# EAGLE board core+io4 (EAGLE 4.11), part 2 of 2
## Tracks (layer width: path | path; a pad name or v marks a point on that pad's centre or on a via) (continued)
N$97
  Bottom 0.254: IC6.2 17.77,68.41 16.5,67.14 12.06,67.14 11.43,67.78 10.16,67.78 8.89,69.05 OUT5-6.10
N$98  (via drill 0.61)
  Top 0.254: v26.03,74.13 26.03,70.32 IC6.5
  Bottom 0.254: v26.03,74.13 19.68,74.13 19.04,73.5 12.06,73.5 11.43,72.86 9.52,72.86 8.89,72.22 8.25,72.22 OUT5-6.12
N$99
  Bottom 0.254: IC6.6 27.93,69.69 26.66,70.95 14.6,70.95 13.97,70.32 7.62,70.32 6.98,70.95 6.98,74.13 7.62,74.13 OUT5-6.14
N$100  (via drill 0.61)
  Top 0.254: v19.68,58.89 v19.68,65.88 | v5.71,53.81 5.71,75.4 v5.08,76.03
  Bottom 0.254: v19.68,65.88 20.95,67.14 35.55,67.14 36.19,67.78 IC6.9 | v19.68,58.89 19.68,55.08 17.77,53.17 8.25,53.17 7.62,53.81 v5.71,53.81 | v5.08,76.03 5.71,76.03 6.34,76.67 7.62,76.67 OUT5-6.16
N$101
  Bottom 0.254: IC15.3 95.24,56.98 96.52,58.25 104.13,58.25 104.77,58.89 116.83,58.89 IN5-6.2
N$102  (via drill 0.61)
  Top 0.254: v97.15,61.43 97.15,57.62 IC15.4
  Bottom 0.254: v97.15,61.43 103.5,61.43 104.77,60.16 106.04,60.16 106.67,60.8 117.47,60.8 IN5-6.4
N$103  (via drill 0.61)
  Top 0.254: v116.2,57.62 115.56,58.25 115.56,62.7 116.83,63.97 IN5-6.6
  Bottom 0.254: v116.2,57.62 115.56,58.25 105.41,58.25 104.77,57.62 IC15.7
N$104  (via drill 0.61)
  Top 0.254: v108.58,65.88 108.58,58.89 107.94,58.25 107.94,56.98 IC15.8
  Bottom 0.254: v108.58,65.88 109.21,66.51 116.83,66.51 IN5-6.8
N$105
  Bottom 0.254: IC16.13 106.67,76.03 103.5,72.86 103.5,72.22 104.13,72.22 105.41,70.95 116.2,70.95 116.83,70.32 118.1,70.32 119.38,69.05 IN5-6.9
N$106  (via drill 0.61)
  Top 0.254: v104.77,83.02 104.77,77.94 IC16.14 | v118.74,83.02 118.74,72.22 119.38,71.59 IN5-6.11
  Bottom 0.254: v104.77,83.02 v118.74,83.02
N$107  (via drill 0.61)
  Top 0.254: v98.42,100.16 98.42,84.29 97.78,83.66 97.78,77.3 IC16.17 | v130.81,100.16 130.81,93.18 130.17,92.55 130.17,74.77 v129.53,74.13
  Bottom 0.254: v98.42,100.16 99.05,99.53 113.66,99.53 114.93,100.8 118.74,100.8 120.01,99.53 130.17,99.53 v130.81,100.16 | v129.53,74.13 120.64,74.13 IN5-6.13
N$108
  Bottom 0.254: IC16.18 95.24,77.3 96.52,78.58 118.74,78.58 120.01,77.3 IN5-6.15
N$109  (via drill 0.61)
  Top 0.254: v104.13,59.52 104.77,60.16 104.77,61.43 106.67,63.34 IC15.13
  Bottom 0.254: v104.13,59.52 106.67,59.52 107.31,60.16 118.1,60.16 118.74,59.52 120.01,59.52 IN5-6.1
N$110  (via drill 0.61)
  Top 0.254: v121.28,79.21 121.28,76.03 120.64,75.4 121.28,74.77 121.28,62.06 120.64,61.43 IN5-6.3 | v106.04,79.84 106.04,72.22 105.41,71.59 105.41,70.95 106.04,70.32 106.04,67.78 104.77,66.51 104.77,65.24 IC15.14
  Bottom 0.254: v121.28,79.21 106.67,79.21 v106.04,79.84
N$111
  Bottom 0.254: IC15.17 97.78,63.34 99.05,62.06 105.41,62.06 106.04,62.7 106.67,62.06 113.66,62.06 116.83,65.24 118.1,65.24 119.38,63.97 IN5-6.5
N$112  (via drill 0.61)
  Top 0.254: v135.88,66.51 136.52,67.14 136.52,67.78 137.16,68.41 137.16,79.84 136.52,80.48 136.52,84.29 v133.98,86.83 | v108.58,87.47 108.58,74.77 109.21,74.13 109.21,70.95 108.58,70.32 108.58,67.78 106.67,65.88 v106.04,65.88
  Bottom 0.254: v135.88,66.51 120.64,66.51 IN5-6.7 | v133.98,86.83 133.34,86.19 114.3,86.19 113.02,87.47 v108.58,87.47 | v106.04,65.88 105.41,66.51 95.88,66.51 94.61,65.24 IC15.18
N$113
  Bottom 0.254: IC8.19 17.77,101.44 16.5,100.16 13.33,100.16 11.43,102.07 OUT7-8.15
N$114
  Bottom 0.254: IC8.16 25.39,101.44 24.12,100.16 17.77,100.16 17.14,99.53 11.43,99.53 OUT7-8.13
N$115
  Bottom 0.254: IC8.15 28.57,100.8 28.57,98.26 12.7,98.26 11.43,96.99 OUT7-8.11
N$116  (via drill 0.61)
  Top 0.254: v12.06,103.97 12.06,95.08 11.43,94.45 OUT7-8.9
  Bottom 0.254: v12.06,103.97 12.7,104.61 34.92,104.61 36.19,103.34 IC8.12
N$117
  Bottom 0.254: IC8.2 17.77,93.81 16.5,92.55 12.06,92.55 11.43,93.18 10.16,93.18 8.89,94.45 OUT7-8.10
N$118  (via drill 0.61)
  Top 0.254: v26.03,99.53 26.03,95.72 IC8.5
  Bottom 0.254: v26.03,99.53 19.68,99.53 19.04,98.89 12.06,98.89 11.43,98.26 9.52,98.26 8.89,97.62 8.25,97.62 OUT7-8.12
N$119
  Bottom 0.254: IC8.6 27.93,95.08 26.66,96.36 14.6,96.36 13.97,95.72 7.62,95.72 6.98,96.36 6.98,99.53 7.62,99.53 OUT7-8.14
N$120
  Top 0.254: IC8.9 36.19,95.72 34.92,96.99 34.92,103.34 33.02,105.25 8.25,105.25 8.25,102.7 OUT7-8.16
N$121  (via drill 0.61)
  Top 0.254: v37.46,84.92 37.46,83.02 36.83,82.39 IC7.9 | v74.92,84.29 77.46,81.75 77.46,80.48 78.73,79.21 78.73,58.89 77.46,57.62 77.46,41.74 76.19,40.48 v76.19,8.09 | v3.17,49.37 2.54,50 2.54,86.83 7.62,91.91 OUT7-8.8
  Bottom 0.254: v37.46,84.92 38.1,84.29 57.15,84.29 57.78,84.92 74.29,84.92 v74.92,84.29 | v76.19,8.09 36.83,8.09 35.55,9.36 27.3,9.36 26.66,10 12.06,10 11.43,9.36 6.34,9.36 1.9,13.81 1.9,49.37 v3.17,49.37
N$122  (via drill 0.61)
  Top 0.254: v6.34,78.58 v6.34,89.37
  Bottom 0.254: v6.34,78.58 9.52,78.58 10.16,79.21 26.03,79.21 27.3,80.48 28.57,80.48 IC7.6 | v6.34,89.37 7.62,89.37 OUT7-8.6
N$123  (via drill 0.61)
  Top 0.254: v9.52,79.84 9.52,84.92 8.89,85.56 8.89,86.83 OUT7-8.4
  Bottom 0.254: v9.52,79.84 25.39,79.84 26.03,80.48 IC7.5
N$124  (via drill 0.61)
  Top 0.254: v50.16,88.73 50.16,80.48 47.62,77.94 47.62,70.32 46.98,69.69 v46.98,58.25 | v52.7,50.63 v52.7,58.25
  Bottom 0.254: v50.16,88.73 78.73,88.73 79.37,88.1 IC24.13 | v52.7,58.25 v46.98,58.25 | v52.7,50.63 58.41,50.63 59.05,50 IC26.5
N$125  (via drill 0.61)
  Top 0.254: v93.34,81.11 93.34,75.4 92.7,74.77 92.7,70.95 93.34,70.32 v93.34,60.8 | v74.92,59.52 75.56,58.89 75.56,50.63 v74.92,50
  Bottom 0.254: v93.34,81.11 92.7,81.75 81.27,81.75 80,80.48 77.46,80.48 77.46,83.02 78.73,84.29 80.64,84.29 81.91,85.56 IC24.14 | v93.34,60.8 77.46,60.8 76.83,61.43 v74.92,59.52 | v74.92,50 74.29,50 73.02,51.27 67.94,51.27 67.3,50.63 66.03,50.63 65.4,50 65.4,46.82 62.23,46.82 61.59,47.46 IC26.6
N$126  (via drill 0.61)
  Top 0.254: v83.81,76.67 83.81,86.19 IC24.15 | v74.29,76.67 73.66,76.03 73.66,66.51 74.29,65.88 74.29,65.24 73.66,64.61 73.66,51.91 v74.29,51.27 | v64.13,51.27 64.13,50 IC26.7
  Bottom 0.254: v74.29,76.67 v83.81,76.67 | v74.29,51.27 73.66,51.91 67.3,51.91 66.67,51.27 v64.13,51.27
N$127  (via drill 0.61)
  Top 0.254: v67.94,72.22 67.94,65.24 72.38,65.24 73.02,64.61 73.02,55.08 67.3,49.37 IC26.8 | v71.11,72.22 70.48,72.86 70.48,78.58 71.75,79.84 71.75,81.75 70.48,83.02 v70.48,98.26 | v86.99,98.26 86.99,88.1 IC24.16
  Bottom 0.254: v67.94,72.22 v71.11,72.22 | v70.48,98.26 74.29,98.26 74.92,97.62 86.35,97.62 v86.99,98.26
N$128  (via drill 0.61)
  Top 0.254: v118.74,47.46 118.74,64.61 118.1,65.24 116.83,65.24 114.93,67.14 114.93,80.48 113.66,81.75 114.93,83.02 114.93,90 114.3,90.64 114.3,98.89 113.66,99.53 v113.66,100.8 | v99.69,100.8 98.42,102.07 98.42,103.34 97.78,103.97 93.34,103.97 93.34,100.8 89.53,96.99 89.53,88.1 IC24.17
  Bottom 0.254: v118.74,47.46 109.21,47.46 108.58,46.82 106.04,46.82 105.41,46.19 104.77,46.19 102.23,48.73 97.15,48.73 96.52,48.09 83.18,48.09 82.55,48.73 74.29,48.73 72.38,50.63 69.84,50.63 69.21,50 IC26.9 | v113.66,100.8 113.02,100.16 100.32,100.16 v99.69,100.8
N$129
  Top 0.254: IC25.3 53.97,70.32 53.97,74.13 52.7,75.4 52.7,79.84 53.97,81.11 53.97,85.56 IC24.3
N$130
  Top 0.254: IC25.4 56.51,70.32 56.51,74.13 55.24,75.4 55.24,84.29 56.51,85.56 IC24.4
N$131
  Top 0.254: IC25.5 59.05,70.32 57.78,71.59 57.78,82.39 59.05,83.66 59.05,85.56 IC24.5
N$132
  Top 0.254: IC25.6 61.59,70.32 60.32,71.59 60.32,84.29 61.59,85.56 IC24.6
N$133
  Top 0.254: IC25.7 64.13,70.32 62.86,71.59 62.86,84.29 64.13,85.56 IC24.7
N$134
  Top 0.254: IC25.8 66.67,70.32 65.4,71.59 65.4,81.11 66.67,82.39 66.67,85.56 IC24.8
N$135
  Top 0.254: IC25.9 69.21,70.32 69.21,74.13 67.94,75.4 67.94,84.29 69.21,85.56 IC24.9
N$136  (via drill 0.61)
  Top 0.254: v92.7,98.89 93.34,98.26 93.34,89.37 93.97,88.73 93.97,87.47 IC24.19 | v67.94,90 v67.94,99.53 | v43.18,88.73 43.18,77.3 43.81,76.67 43.18,76.03 43.18,72.22 43.81,71.59 43.81,62.06 43.18,61.43 43.18,58.25 45.08,56.35 45.08,55.71 48.89,51.91 48.89,50 IC26.1
  Bottom 0.254: v92.7,98.89 90.16,98.89 89.53,99.53 v67.94,99.53 | v67.94,90 46.35,90 45.72,89.37 43.81,89.37 v43.18,88.73
N$137  (via drill 0.61)
  Top 0.254: v52.7,81.11 52.7,90.64 51.43,91.91 51.43,100.8 IC24.39 | v73.02,81.11 73.02,73.5 v72.38,72.86
  Bottom 0.254: v52.7,81.11 53.34,80.48 69.84,80.48 70.48,81.11 v73.02,81.11 | v72.38,72.86 72.38,72.22 71.11,70.95 58.41,70.95 57.78,70.32 57.78,67.78 57.15,67.14 49.53,67.14 48.89,67.78 IC25.1
N$138  (via drill 0.61)
  Top 0.254: v50.8,91.28 50.8,100.16 49.53,101.44 IC24.40 | v123.19,88.73 123.19,77.3 123.82,76.67 123.82,58.89 v123.19,58.25 | v163.82,18.25 163.82,12.54 164.46,11.9 164.46,9.36 167,6.82 167,4.92 167.63,4.28 173.98,4.28 173.98,4.92 174.62,5.55 174.62,6.18 173.98,6.82 173.98,10 174.62,10.63 IC27.9
  Bottom 0.254: v50.8,91.28 66.03,91.28 66.67,90.64 67.3,90.64 67.94,91.28 78.1,91.28 78.73,90.64 79.37,91.28 86.99,91.28 88.26,90 96.52,90 97.15,89.37 115.56,89.37 116.2,88.73 v123.19,88.73 | v123.19,58.25 124.45,56.98 133.98,56.98 134.62,57.62 136.52,57.62 139.06,55.08 139.06,52.54 130.81,52.54 128.9,50.63 128.9,18.88 146.68,18.88 147.31,18.25 v163.82,18.25
N$140
  Top 0.254: IC27.8 177.16,8.09 177.79,8.09 C4.1 | IC27.12 176.53,17.61 182.88,11.27 182.88,10.63 R4.1
  Bottom 0.254: R4.1 182.88,10.63 180.34,8.09 179.06,8.09 C4.1
N$141
  Top 0.254: R4.2 182.88,18.25 181.6,18.25 R3.1 180.97,18.88 180.97,20.79 177.16,20.79 IC27.13
N$142
  Bottom 0.254: IC27.11 177.16,15.71 185.41,15.71 C5.1
N$143
  Top 0.254: R10.1 167.63,3.01 166.37,4.28 166.37,4.92 R11.E
N$144
  Bottom 0.254: X1.4 142.87,15.08 143.5,14.44 148.59,14.44 149.22,13.81 X1.6
N$145
  Top 0.254: X1.8 144.78,13.17 146.04,13.17 X1.7
N$146
  Top 0.254: X1.5 139.69,15.08 135.25,15.08 X1.G2
  Bottom 0.254: X1.G1 155.57,15.08 153.66,16.98 140.97,16.98 140.33,16.34 X1.5
N$147  (via drill 0.61)
  Top 0.254: IC18.13 206.37,17.61 206.37,16.34 IC18.12 | v183.51,46.19 183.51,47.46 179.7,47.46 179.06,48.09 179.06,50 182.24,50 182.88,50.63 182.88,56.98 182.24,57.62 182.88,58.25 182.88,62.06 187.95,67.14 187.95,79.84 188.59,80.48 188.59,83.02 IC21.5 | v191.76,46.19 191.13,45.55 191.13,34.76 191.76,34.12 191.76,31.58 192.4,30.95 v192.4,19.52
  Bottom 0.254: v183.51,46.19 v191.76,46.19 | v192.4,19.52 200.66,19.52 201.92,18.25 205.1,18.25 IC18.13
N$148
  Top 0.254: LED1.K 208.91,11.27 207.64,12.54 207.64,13.17 IC18.11
N$149
  Bottom 0.254: R12.1 179.06,18.25 180.34,16.98 192.4,16.98 197.48,11.9 202.56,11.9 205.1,9.36 209.54,9.36 210.81,10.63 LED1.A
N$150
  Top 0.254: R13.2 176.53,104.61 177.79,104.61 JP2.1 178.43,103.34 178.43,100.8 IC21.24
N$151
  Bottom 0.254: IC28.4 202.56,58.89 207,54.45 207,52.54 210.18,52.54 214.62,48.09 214.62,7.46 210.81,7.46 208.91,5.55 207.64,5.55 IC18.8
N$152  (via drill 0.61)
  Top 0.254: v203.19,45.55 203.19,34.12 202.56,33.49 IC19.5 | v207.64,45.55 207,46.19 207,63.34 207.64,63.97 IC28.15
  Bottom 0.254: v207.64,45.55 v203.19,45.55
N$153
  Top 0.254: IC20.7 154.94,25.23 156.2,25.23 IC20.8
N$154
  Bottom 0.254: C7.1 147.31,20.79 147.95,20.15 166.37,20.15 167.63,18.88 IC27.3
N$155
  Top 0.254: IC20.5 149.85,26.5 154.94,31.58 158.75,31.58 158.75,33.49 C9.2
N$156
  Bottom 0.254: IC20.4 147.31,26.5 149.22,28.41 158.75,28.41 C9.1
N$157
  Bottom 0.254: C8.2 137.16,30.95 140.33,27.77 142.23,27.77 143.5,26.5 IC20.3
N$158
  Top 0.254: C8.1 137.16,25.87 138.42,25.87 IC20.1
N$159
  Bottom 0.254: C11.1 147.31,23.33 147.95,23.96 149.85,23.96 151.12,25.23 IC20.6
N$160
  Top 0.254: C10.2 139.69,23.33 140.97,24.6 140.97,25.23 IC20.2
NMI\
  Top 0.254: R6.1 179.06,61.43 179.7,61.43 IC17.6 181.6,62.06 187.32,67.78 187.32,86.19 191.76,86.19 193.03,84.92 IC21.7
OUT00
  Top 0.254: IC1.11 38.73,11.9 42.54,8.09 42.54,5.55 43.81,4.28 45.08,4.28 45.08,25.87 46.35,27.14 IC10.1
OUT01
  Bottom 0.254: IC2.11 39.37,26.5 46.98,26.5 48.26,27.77 IC10.2
OUT02  (via drill 0.61)
  Top 0.254: v52.7,37.3 52.07,36.66 52.07,29.04 IC10.3
  Bottom 0.254: v52.7,37.3 38.73,37.3 IC3.11
OUT03  (via drill 0.61)
  Top 0.254: v55.24,36.03 54.61,35.39 54.61,29.04 IC10.4 | v37.46,36.66 37.46,45.55 38.73,46.82 38.73,50 IC4.11
  Bottom 0.254: v55.24,36.03 52.7,36.03 52.07,36.66 v37.46,36.66
OUT04  (via drill 0.61)
  Top 0.254: v57.78,39.84 57.15,39.2 57.15,29.04 IC10.5 | v42.54,39.84 41.91,40.48 41.91,43.02 41.27,43.65 41.27,63.34 v41.91,63.97
  Bottom 0.254: v57.78,39.84 57.15,39.2 45.08,39.2 44.45,39.84 v42.54,39.84 | v41.91,63.97 39.37,63.97 IC5.11
OUT05  (via drill 0.61)
  Top 0.254: v50.16,30.95 50.8,31.58 50.8,40.48 v50.16,41.11 | v43.18,41.11 42.54,41.11 42.54,44.28 43.18,44.92 43.18,55.71 42.54,56.35 42.54,62.06 43.18,62.7 43.18,63.97 41.27,65.88 41.27,68.41 43.18,70.32 43.18,70.95 42.54,71.59 v42.54,76.67
  Bottom 0.254: v50.16,30.95 57.78,30.95 59.05,29.68 IC10.6 | v50.16,41.11 v43.18,41.11 | v42.54,76.67 39.37,76.67 IC6.11
OUT06  (via drill 0.61)
  Top 0.254: v43.18,104.61 v43.18,90 | v70.48,103.97 70.48,99.53 71.75,98.26 71.75,89.37 73.02,88.1 73.02,84.92 76.19,81.75 76.19,75.4 78.1,73.5 78.1,59.52 76.83,58.25 76.83,42.38 75.56,41.11 75.56,26.5 v74.92,25.87
  Bottom 0.254: v43.18,90 42.54,89.37 39.37,89.37 IC7.11 | v43.18,104.61 43.18,105.25 61.59,105.25 62.23,104.61 69.84,104.61 v70.48,103.97 | v74.92,25.87 74.29,26.5 62.23,26.5 61.59,27.14 IC10.7
OUT07  (via drill 0.61)
  Top 0.254: v38.73,96.99 38.73,100.8 IC8.11 | v74.29,95.72 74.29,93.18 75.56,91.91 75.56,84.92 78.1,82.39 78.1,81.11 79.37,79.84 79.37,58.25 78.1,56.98 78.1,32.85 v77.46,32.22 | v64.13,32.22 64.13,29.68 IC10.8
  Bottom 0.254: v38.73,96.99 55.24,96.99 56.51,95.72 v74.29,95.72 | v77.46,32.22 76.83,31.58 64.77,31.58 v64.13,32.22
PIA-A0  (via drill 0.61)
  Top 0.254: IC1.3 21.58,6.18 22.22,6.82 22.22,15.08 20.95,16.34 20.95,16.98 IC2.3 21.58,18.88 21.58,23.96 22.22,24.6 22.22,27.77 20.95,29.04 20.95,29.68 IC3.3 21.58,31.58 21.58,36.66 22.22,37.3 22.22,40.48 20.95,41.74 20.95,42.38 IC4.3 21.58,44.28 21.58,49.37 22.22,50 22.22,53.17 20.95,54.45 20.95,55.08 IC5.3 21.58,56.98 21.58,59.52 | 21.58,59.52 21.58,62.06 22.22,62.7 22.22,65.88 20.95,67.14 20.95,67.78 IC6.3 21.58,69.69 21.58,74.77 22.22,75.4 22.22,78.58 20.95,79.84 20.95,80.48 IC7.3 21.58,82.39 21.58,87.47 22.22,88.1 22.22,91.28 20.95,92.55 20.95,93.18 IC8.3 | IC11.2 92.7,6.18 93.34,6.82 93.34,14.44 92.7,15.08 92.7,15.71 92.07,16.34 92.07,16.98 IC12.2 92.7,18.88 92.7,23.96 93.34,24.6 93.34,27.14 92.7,27.77 92.7,28.41 92.07,29.04 92.07,29.68 IC13.2 92.7,31.58 92.7,36.66 93.34,37.3 93.34,39.84 92.7,40.48 92.7,41.11 92.07,41.74 92.07,42.38 IC14.2 | v84.45,56.35 v84.45,41.74 | v45.08,74.77 45.08,73.5 44.45,72.86 v44.45,61.43 | v76.83,60.16 77.46,60.16 77.46,72.86 v76.83,73.5 | 21.58,59.52 v22.22,59.52
  Bottom 0.254: 88.89,58.25 91.44,58.25 92.07,57.62 IC15.2 | 88.89,58.25 87.62,56.98 86.35,56.98 85.72,56.35 v84.45,56.35 | v84.45,41.74 91.44,41.74 92.07,42.38 IC14.2 | 53.34,74.77 53.97,75.4 IC25.18 | v45.08,74.77 53.34,74.77 | SV9.1 48.26,61.43 v44.45,61.43 31.11,61.43 28.57,58.89 22.86,58.89 v22.22,59.52 | 76.83,74.13 69.21,74.13 68.57,74.77 53.34,74.77 | 76.83,74.13 81.91,74.13 83.18,72.86 87.62,72.86 88.26,72.22 88.89,72.86 92.07,72.86 92.07,70.32 IC16.2 | 88.89,58.25 88.89,60.16 v76.83,60.16 | 76.83,74.13 v76.83,73.5
PIA-A1  (via drill 0.61)
  Top 0.254: IC16.5 100.32,68.41 100.32,65.88 100.96,65.24 100.96,58.89 100.32,58.25 100.32,56.98 IC15.5 100.32,55.71 100.32,53.17 100.96,52.54 100.96,46.19 100.32,45.55 100.32,44.28 IC14.5 100.32,43.02 100.32,40.48 100.96,39.84 100.96,33.49 100.32,32.85 100.32,31.58 IC13.5 100.32,30.31 100.32,27.77 100.96,27.14 100.96,20.79 100.32,20.15 100.32,18.88 IC12.5 99.69,16.98 99.69,15.71 100.96,14.44 100.96,10 100.32,9.36 100.32,6.18 IC11.5 99.69,4.28 v99.69,2.38 | 24.76,14.44 24.76,10 24.12,9.36 24.12,6.18 IC1.4 | 24.76,14.44 23.49,15.71 23.49,16.98 IC2.4 23.49,19.52 23.49,23.33 24.76,24.6 24.76,27.14 23.49,28.41 23.49,29.68 IC3.4 23.49,32.22 23.49,36.03 24.76,37.3 24.76,39.84 23.49,41.11 23.49,42.38 IC4.4 23.49,44.92 23.49,48.73 24.76,50 24.76,52.54 23.49,53.81 23.49,55.08 IC5.4 24.12,56.98 24.12,62.06 24.76,62.7 24.76,65.24 23.49,66.51 23.49,67.78 IC6.4 23.49,70.32 23.49,74.13 24.76,75.4 24.76,77.94 23.49,79.21 23.49,80.48 IC7.4 24.12,82.39 24.76,83.02 24.76,90.64 23.49,91.91 23.49,93.18 IC8.4 | v57.78,83.66 57.15,83.02 57.15,77.3 IC25.17 | v48.89,73.5 50.16,72.22 50.16,64.61 49.53,63.97 SV9.2 | v27.3,3.64 27.3,14.44 26.66,15.08 24.76,15.08 24.76,14.44
  Bottom 0.254: 32.38,83.66 24.12,83.66 23.49,83.02 IC7.4 | 32.38,83.66 v57.78,83.66 | v48.89,73.5 38.73,73.5 37.46,74.77 33.02,74.77 32.38,75.4 32.38,83.66 | v99.69,2.38 99.05,1.74 40.64,1.74 38.73,3.64 v27.3,3.64
PIA-A2  (via drill 0.61)
  Top 0.254: v95.88,20.15 v95.88,3.64 | IC12.6 102.23,19.52 102.23,23.33 103.5,24.6 103.5,29.68 102.86,30.31 IC13.6 102.23,32.22 102.23,36.03 103.5,37.3 103.5,42.38 102.86,43.02 IC14.6 102.23,44.92 102.23,48.73 103.5,50 103.5,55.08 102.86,55.71 IC15.6 102.23,57.62 102.23,61.43 103.5,62.7 103.5,67.78 102.86,68.41 IC16.6 | IC1.7 31.74,6.18 32.38,6.82 32.38,15.08 31.74,15.71 31.74,17.61 IC2.7 31.74,18.88 31.74,23.96 32.38,24.6 | 32.38,24.6 32.38,27.77 31.74,28.41 31.74,30.31 IC3.7 31.74,31.58 31.74,36.66 32.38,37.3 32.38,40.48 31.74,41.11 31.74,43.02 IC4.7 31.74,44.28 31.74,49.37 32.38,50 32.38,53.17 31.74,53.81 31.74,55.71 IC5.7 31.74,56.98 31.74,60.16 | 31.74,60.16 31.74,62.06 32.38,62.7 32.38,65.88 31.74,66.51 31.74,68.41 IC6.7 31.74,69.69 31.74,74.77 32.38,75.4 32.38,78.58 31.74,79.21 31.74,81.11 IC7.7 31.74,82.39 31.74,87.47 32.38,88.1 32.38,91.28 31.74,91.91 31.74,93.81 IC8.7 | v60.32,93.18 60.32,85.56 59.69,84.92 59.69,77.3 IC25.16 | 31.74,60.16 v32.38,60.16 | v77.46,23.96 v77.46,21.42 | 32.38,24.6 v32.38,23.96
  Bottom 0.254: v95.88,3.64 95.88,6.82 96.52,7.46 101.59,7.46 102.23,6.82 IC11.6 | IC12.6 102.23,19.52 101.59,20.15 v95.88,20.15 95.88,21.42 94.61,22.7 80,22.7 79.37,22.06 78.1,22.06 v77.46,21.42 | v60.32,93.18 43.81,93.18 43.18,92.55 31.74,92.55 31.11,93.18 IC8.7 | v32.38,60.16 33.02,60.8 43.81,60.8 44.45,60.16 50.8,60.16 51.43,60.8 SV9.3 | v77.46,23.96 76.83,23.33 34.29,23.33 33.65,23.96 v32.38,23.96
PIA-A3  (via drill 0.61)
  Top 0.254: 111.12,16.98 110.48,17.61 IC12.9 | 111.12,16.98 111.12,10 109.85,8.73 109.85,6.82 IC11.9 | 111.12,29.68 110.48,30.31 IC13.9 | 111.12,29.68 111.12,16.98 | 111.12,42.38 110.48,43.02 IC14.9 | 111.12,42.38 111.12,29.68 | 111.12,55.08 110.48,55.71 IC15.9 | 111.12,55.08 111.12,42.38 | 111.12,55.08 111.12,67.78 110.48,68.41 IC16.9 110.48,69.69 112.39,71.59 v112.39,72.86 | v61.59,73.5 61.59,75.4 IC25.15 62.23,77.3 62.23,84.92 62.86,85.56 62.86,105.88 78.1,105.88 80.64,103.34 80.64,94.45 v81.91,93.18 | v52.7,72.22 52.7,67.78 51.43,66.51 51.43,64.61 SV9.4 | 34.92,16.98 34.29,17.61 IC2.8 | 34.92,16.98 34.92,10 33.65,8.73 33.65,6.82 IC1.8 | 34.92,29.68 34.29,30.31 IC3.8 | 34.92,16.98 34.92,29.68 | 34.92,42.38 34.29,43.02 IC4.8 | 34.92,29.68 34.92,42.38 | 34.92,55.08 34.29,55.71 IC5.8 | 34.92,42.38 34.92,55.08 | 34.92,67.78 34.29,68.41 IC6.8 | 34.92,55.08 v34.92,65.88 34.92,67.78 | 34.92,80.48 34.29,81.11 IC7.8 | 34.92,67.78 34.92,80.48 | 34.92,80.48 34.92,93.18 34.29,93.81 IC8.8 | v116.2,72.86 115.56,73.5 115.56,77.3 116.2,77.94 v116.2,91.28
  Bottom 0.254: v61.59,73.5 60.32,72.22 v52.7,72.22 | v34.92,65.88 39.37,65.88 40,65.24 50.8,65.24 51.43,64.61 SV9.4 | v116.2,72.86 v112.39,72.86 | v116.2,91.28 113.66,93.81 82.55,93.81 v81.91,93.18
PIA-A4  (via drill 0.61)
  Top 0.254: IC15.12 109.21,63.34 109.21,58.25 108.58,57.62 108.58,52.54 109.21,51.91 IC14.12 109.21,50.63 109.21,48.73 108.58,48.09 108.58,41.74 | v116.2,14.44 115.56,15.08 115.56,25.23 116.2,25.87 116.2,27.77 117.47,29.04 116.2,30.31 116.2,36.66 116.83,37.3 118.1,37.3 118.74,37.94 v118.74,39.84 | IC12.12 109.21,26.5 108.58,27.14 108.58,32.22 109.21,32.85 109.21,37.94 IC13.12 109.85,39.84 109.85,41.74 108.58,41.74 | v109.85,91.91 109.85,87.47 109.21,86.83 109.21,77.3 IC16.12 | v90.8,91.91 90.8,72.86 85.08,67.14 85.08,59.52 85.72,58.89 85.72,49.37 88.26,46.82 v88.26,36.66 | v106.04,40.48 107.31,40.48 108.58,41.74 | 33.65,23.33 32.38,22.06 32.38,16.34 33.02,15.71 33.02,13.81 IC1.13 | 33.65,23.33 33.65,24.6 IC2.13 33.02,26.5 33.02,28.41 32.38,29.04 32.38,36.03 33.02,36.66 33.02,37.94 IC3.13 33.02,39.2 33.02,41.11 32.38,41.74 32.38,48.73 33.02,49.37 33.02,50.63 IC4.13 33.02,51.91 33.02,53.81 32.38,54.45 32.38,58.89 33.65,60.16 33.65,62.7 IC5.13 33.02,64.61 33.02,66.51 32.38,67.14 32.38,74.13 33.02,74.77 33.02,76.03 IC6.13 | IC6.13 33.02,77.3 33.02,79.21 32.38,79.84 32.38,86.83 33.02,87.47 33.02,88.73 IC7.13 33.02,90 33.02,91.91 32.38,92.55 32.38,95.72 33.65,96.99 33.65,100.8 IC8.13 | v33.65,79.21 33.65,77.94 IC6.13 | v95.88,23.33 v95.88,36.66 | 33.65,23.33 v33.65,22.7
  Bottom 0.254: v116.2,14.44 115.56,15.08 109.85,15.08 109.85,14.44 IC11.12 | v118.74,39.84 116.2,39.84 115.56,40.48 109.85,40.48 109.85,39.84 IC13.12 | v109.85,91.91 109.21,92.55 91.44,92.55 v90.8,91.91 | 95.24,36.66 v88.26,36.66 | 95.24,36.66 95.88,37.3 95.88,41.11 105.41,41.11 v106.04,40.48 | v33.65,79.21 62.86,79.21 64.13,77.94 IC25.14 | SV9.5 53.97,62.06 52.7,62.06 52.07,62.7 44.45,62.7 43.81,62.06 34.29,62.06 33.65,62.7 IC5.13 | v95.88,36.66 95.24,36.66 | v95.88,23.33 78.1,23.33 77.46,22.7 v33.65,22.7
PIA-A5  (via drill 0.61)
  Top 0.254: IC1.14 30.47,13.81 29.84,14.44 29.84,20.79 31.11,22.06 31.11,24.6 IC2.14 30.47,26.5 29.84,27.14 29.84,33.49 31.11,34.76 31.11,37.3 IC3.14 30.47,39.2 29.84,39.84 29.84,46.19 31.11,47.46 31.11,50 IC4.14 30.47,51.91 29.84,52.54 29.84,57.62 31.11,58.89 31.11,62.7 IC5.14 30.47,64.61 29.84,65.24 29.84,71.59 31.11,72.86 31.11,75.4 IC6.14 31.11,77.94 31.11,79.21 29.84,80.48 29.84,84.29 31.11,85.56 31.11,88.1 IC7.14 30.47,90 29.84,90.64 29.84,96.99 31.11,98.26 31.11,100.8 IC8.14 | IC11.15 101.59,13.81 101.59,15.08 100.96,15.71 100.96,19.52 101.59,20.15 101.59,25.23 IC12.15 101.59,26.5 101.59,27.77 100.96,28.41 100.96,32.22 101.59,32.85 101.59,37.94 IC13.15 101.59,39.2 101.59,40.48 100.96,41.11 100.96,44.92 101.59,45.55 101.59,50.63 IC14.15 101.59,51.91 101.59,53.17 100.96,53.81 100.96,57.62 101.59,58.25 101.59,63.34 IC15.15 101.59,64.61 101.59,65.88 100.96,66.51 100.96,70.95 102.23,72.22 102.23,75.4 IC16.15 102.23,77.94 v102.23,79.84 | v55.24,70.95 55.24,64.61 54.61,63.97 SV9.6 | v66.67,73.5 66.67,75.4 IC25.13 | v41.91,90.64 41.27,90 41.27,70.95 v41.91,70.32
  Bottom 0.254: v102.23,79.84 101.59,79.21 71.75,79.21 71.11,78.58 67.3,78.58 66.67,77.94 IC25.13 | v66.67,73.5 62.86,73.5 60.96,71.59 55.88,71.59 v55.24,70.95 47.62,70.95 46.98,70.32 v41.91,70.32 | v41.91,90.64 41.27,91.28 31.74,91.28 31.11,90.64 IC7.14
PIA-A6  (via drill 0.61)
  Top 0.254: IC11.16 99.05,13.81 99.05,15.71 98.42,16.34 98.42,19.52 99.69,20.79 99.69,24.6 IC12.16 99.69,27.14 99.69,28.41 98.42,29.68 98.42,32.22 99.69,33.49 99.69,37.3 IC13.16 99.69,39.84 99.69,41.11 98.42,42.38 98.42,44.92 99.69,46.19 99.69,50 IC14.16 99.69,52.54 99.69,53.81 98.42,55.08 98.42,57.62 99.69,58.89 v99.69,59.52 99.69,62.7 IC15.16 99.69,65.24 99.69,66.51 98.42,67.78 98.42,70.32 99.69,71.59 99.69,75.4 IC16.16 | IC1.17 22.86,13.81 22.86,15.71 22.22,16.34 22.22,23.33 22.86,23.96 22.86,25.23 IC2.17 22.86,26.5 22.86,28.41 22.22,29.04 22.22,36.03 22.86,36.66 22.86,37.94 IC3.17 22.86,39.2 22.86,41.11 22.22,41.74 22.22,48.73 22.86,49.37 22.86,50.63 IC4.17 22.86,51.91 22.86,53.81 22.22,54.45 22.22,58.25 23.49,59.52 23.49,62.7 IC5.17 22.86,64.61 22.86,66.51 22.22,67.14 22.22,74.13 22.86,74.77 22.86,76.03 IC6.17 22.86,77.3 22.86,79.21 22.22,79.84 22.22,86.83 22.86,87.47 22.86,88.73 IC7.17 | v70.48,67.14 70.48,70.32 69.84,70.95 69.84,76.03 IC25.12 69.84,77.3 69.84,79.21 v70.48,79.84 | v60.32,67.14 v60.32,62.7 | IC8.17 23.49,100.8 23.49,96.99 22.22,95.72 22.22,92.55 22.86,91.91 22.86,90 IC7.17 | v45.08,85.56 v45.08,80.48 | v23.49,85.56 23.49,88.1 IC7.17 | v90.8,59.52 90.8,65.88 v90.16,66.51
  Bottom 0.254: v60.32,67.14 60.96,66.51 69.84,66.51 v70.48,67.14 89.53,67.14 v90.16,66.51 | v60.32,62.7 57.78,62.7 57.15,62.06 56.51,62.06 SV9.7 | v70.48,79.84 45.72,79.84 v45.08,80.48 | v45.08,85.56 44.45,86.19 24.12,86.19 v23.49,85.56 | v90.8,59.52 v99.69,59.52
PIA-A7  (via drill 0.61)
  Top 0.254: IC11.19 92.07,14.44 92.07,15.08 90.8,16.34 90.8,19.52 92.07,20.79 92.07,24.6 IC12.19 92.07,27.14 92.07,27.77 90.8,29.04 90.8,32.22 92.07,33.49 92.07,37.3 IC13.19 92.07,39.84 92.07,40.48 90.8,41.74 90.8,44.92 92.07,46.19 92.07,50 IC14.19 92.07,52.54 92.07,53.17 90.8,54.45 90.8,57.62 92.07,58.89 92.07,62.7 IC15.19 92.07,65.24 92.07,65.88 90.8,67.14 90.8,70.32 92.07,71.59 92.07,75.4 IC16.19 | IC1.18 20.95,14.44 20.95,15.08 19.68,16.34 19.68,19.52 20.95,20.79 20.95,24.6 IC2.18 20.95,27.14 20.95,27.77 19.68,29.04 19.68,32.22 20.95,33.49 20.95,37.3 IC3.18 20.95,39.84 20.95,40.48 19.68,41.74 19.68,44.92 20.95,46.19 20.95,50 IC4.18 20.95,52.54 20.95,53.17 19.68,54.45 19.68,57.62 20.95,58.89 20.95,62.7 IC5.18 20.95,65.24 20.95,65.88 19.68,67.14 19.68,70.32 20.95,71.59 20.95,75.4 IC6.18 20.95,77.94 20.95,78.58 19.68,79.84 19.68,83.02 20.95,84.29 20.95,88.1 IC7.18 20.95,90.64 20.95,91.28 19.68,92.55 19.68,95.72 20.95,96.99 20.95,100.8 IC8.18 | v55.24,53.17 55.24,63.34 55.88,63.97 SV9.8
  Bottom 0.254: IC25.11 71.75,77.94 72.38,78.58 91.44,78.58 92.07,77.94 IC16.19 | IC4.18 20.95,52.54 21.58,53.17 v55.24,53.17 55.88,52.54 59.05,52.54 60.32,53.81 60.96,53.17 65.4,53.17 66.03,53.81 66.67,53.81 67.94,52.54 88.26,52.54 88.89,53.17 91.44,53.17 92.07,52.54 IC14.19
PIA-B0  (via drill 0.61)
  Top 0.254: IC9.23 48.26,21.42 47.62,22.06 47.62,37.94 48.89,39.2 48.89,42.38 IC10.23 48.89,44.92 48.89,46.19 50.16,47.46 v50.16,54.45 | v65.4,65.24 65.4,62.06 64.77,61.43 SV9.13 | v52.7,65.88 52.7,60.8 53.97,59.52 53.97,57.62 IC26.18
  Bottom 0.254: v50.16,54.45 53.34,54.45 53.97,55.08 IC26.18 | v65.4,65.24 64.77,65.24 64.13,65.88 58.41,65.88 57.78,66.51 57.15,65.88 v52.7,65.88
PIA-B1  (via drill 0.61)
  Top 0.254: IC10.22 51.43,42.38 51.43,30.95 50.16,29.68 50.16,25.23 51.43,23.96 51.43,22.06 IC9.22 | v55.24,45.55 55.24,51.27 56.51,52.54 56.51,55.08 IC26.17 57.15,56.98 57.78,57.62 v57.78,65.24
  Bottom 0.254: v55.24,45.55 52.07,45.55 51.43,44.92 IC10.22 | v57.78,65.24 63.5,65.24 64.13,64.61 SV9.14
PIA-B2  (via drill 0.61)
  Top 0.254: IC9.21 53.34,21.42 52.7,22.06 52.7,36.03 53.97,37.3 53.97,42.38 IC10.21 | v57.78,41.74 57.78,53.17 59.05,54.45 59.05,55.08 IC26.16 59.05,57.62 v59.05,58.89
  Bottom 0.254: v57.78,41.74 54.61,41.74 53.97,42.38 IC10.21 | v59.05,58.89 60.32,58.89 61.59,60.16 66.03,60.16 66.67,60.8 SV9.15
PIA-B3  (via drill 0.61)
  Top 0.254: v62.86,62.7 62.86,57.62 62.23,56.98 IC26.15 61.59,55.08 v61.59,51.27 | IC10.20 56.51,42.38 56.51,30.95 55.24,29.68 55.24,25.23 56.51,23.96 56.51,22.06 IC9.20
  Bottom 0.254: v62.86,62.7 66.03,62.7 66.67,63.34 SV9.16 | v61.59,51.27 60.32,50 60.32,46.19 59.05,46.19 57.78,44.92 56.51,44.92 IC10.20
PIA-B4  (via drill 0.61)
  Top 0.254: v66.67,59.52 66.67,58.89 64.77,56.98 IC26.14 64.13,55.08 64.13,52.54 62.86,51.27 62.86,22.06 62.23,21.42 IC9.18
  Bottom 0.254: v66.67,59.52 67.94,60.8 67.94,61.43 68.57,61.43 SV9.17
PIA-B5  (via drill 0.61)
  Top 0.254: v60.32,52.54 60.32,44.92 60.96,44.28 IC10.18 | v66.67,52.54 66.67,55.08 IC26.13 67.3,56.98 67.94,57.62 67.94,63.34 68.57,63.97 SV9.18
  Bottom 0.254: v60.32,52.54 v66.67,52.54
PIA-B6  (via drill 0.61)
  Top 0.254: v69.21,59.52 69.21,57.62 IC26.12 | v71.75,59.52 71.75,60.8 SV9.19
  Bottom 0.254: v69.21,59.52 v71.75,59.52
PIA-B7
  Top 0.254: IC26.11 71.75,57.62 70.48,58.89 70.48,62.06 71.75,63.34 SV9.20
R/W\  (via drill 0.61)
  Top 0.254: v213.35,60.16 214.62,61.43 214.62,98.26 v213.35,99.53 | v97.15,90.64 97.15,100.8 IC24.21 | v113.02,86.19 v113.02,90.64 | v206.37,89.37 206.37,98.26 IC21.13 | v133.98,85.56 v133.98,63.34
  Bottom 0.254: v213.35,60.16 198.75,60.16 198.12,59.52 196.84,59.52 IC17.34 | v213.35,99.53 207,99.53 IC21.13 | v97.15,90.64 97.78,90 112.39,90 v113.02,90.64 | v113.02,86.19 113.66,85.56 v133.98,85.56 137.16,88.73 160.01,88.73 161.28,90 163.19,90 163.82,90.64 197.48,90.64 198.12,90 200.66,90 201.29,89.37 v206.37,89.37 | v133.98,63.34 139.69,63.34 140.33,62.7 IC22.27
RST\  (via drill 0.61)
  Top 0.254: v212.72,74.77 210.18,72.22 210.18,67.78 210.81,67.14 v210.81,46.82 | v203.83,46.82 204.47,46.19 204.47,26.5 201.92,23.96 201.92,8.73 v202.56,8.09 | v65.4,82.39 65.4,88.1 63.5,90 63.5,101.44 IC24.34 | v94.61,83.02 v94.61,80.48 | v196.21,77.94 196.21,74.77 IC17.40
  Bottom 0.254: v212.72,74.77 201.29,74.77 200.66,74.13 197.48,74.13 IC17.40 | v210.81,46.82 v203.83,46.82 | v202.56,8.09 200.02,8.09 IC18.6 | v65.4,82.39 73.02,82.39 75.56,79.84 93.34,79.84 93.97,80.48 v94.61,80.48 | v94.61,83.02 94.61,82.39 101.59,82.39 104.13,84.92 110.48,84.92 111.75,83.66 118.1,83.66 118.74,84.29 121.28,81.75 126.99,81.75 130.81,77.94 132.71,77.94 133.34,78.58 176.53,78.58 177.16,77.94 v196.21,77.94
RX  (via drill 0.61)
  Top 0.254: v151.76,52.54 151.76,43.65 151.12,43.02 151.12,35.39 149.85,34.12 IC20.12 | v175.25,82.39 v175.25,53.17
  Bottom 0.254: v151.76,52.54 152.39,53.17 161.28,53.17 161.92,53.81 172.72,53.81 173.98,52.54 174.62,52.54 v175.25,53.17 | v175.25,82.39 180.34,82.39 180.97,83.02 IC21.2
RXD
  Top 0.254: IC20.13 146.68,32.22 147.95,30.95 147.95,16.34 X1.2
TX  (via drill 0.61)
  Top 0.254: v186.05,29.68 186.05,39.84 185.41,40.48 185.41,54.45 v186.05,55.08 | v188.59,57.62 188.59,79.21 191.13,81.75 191.13,83.02 IC21.6
  Bottom 0.254: v186.05,29.68 174.62,29.68 172.72,31.58 152.39,31.58 151.76,32.22 IC20.11 | v188.59,57.62 v186.05,55.08
TXD
  Top 0.254: IC20.14 144.14,32.22 145.41,30.95 145.41,16.34 X1.3
VCC  (via drill 0.61)
  Top 0.508: v84.45,13.17 v84.45,25.87 v84.45,38.57 | v95.88,49.37 95.88,42.38 v94.61,41.11 | IC24.24 90.16,102.7 92.07,104.61 98.42,104.61 100.96,102.07 100.96,100.16 99.05,98.26 99.05,84.29 R14.2 | IC24.22 94.61,100.8 94.61,91.28 97.15,88.73 97.15,88.1 IC24.20 97.15,85.56 v97.15,84.29 97.15,79.21 95.88,77.94 v95.88,73.5 | SV9.12 61.59,63.34 61.59,62.06 SV9.11 61.59,60.8 v61.59,58.89 | v89.53,74.13 89.53,75.4 IC16.20 | v78.73,25.87 79.37,26.5 79.37,55.71 v80,56.35 | v5.08,18.25 v5.08,11.9 | v5.08,38.57 v5.08,20.79 | IC2.20 15.24,26.5 15.24,27.77 14.6,28.41 14.6,33.49 15.87,34.76 15.87,37.3 IC3.20 15.87,39.84 15.87,40.48 14.6,41.74 14.6,45.55 15.87,46.82 15.87,50 IC4.20 | BYP4.1 13.33,51.91 13.33,53.17 14.6,54.45 14.6,62.7 15.24,63.34 IC5.20 15.24,64.61 14.6,65.24 14.6,72.22 15.87,73.5 15.87,75.4 IC6.20 15.24,77.3 14.6,77.94 14.6,86.19 15.87,87.47 15.87,88.1 IC7.20 | BYP9.1 43.81,21.42 43.81,29.04 45.08,30.31 45.08,37.94 46.35,39.2 46.35,42.38 IC10.24 | v43.81,56.35 43.81,44.28 BYP10.1 | BYP24.1 46.98,91.91 47.62,91.28 47.62,79.21 46.35,77.94 46.35,77.3 BYP25.1 46.35,76.03 46.35,73.5 45.08,72.22 45.08,62.7 45.72,62.06 45.72,56.35 BYP26.1 | IC8.20 15.87,100.8 15.87,97.62 14.6,96.36 14.6,92.55 13.33,91.28 13.33,90 BYP7.1 | v46.35,24.6 46.35,22.06 IC9.24 | R8.2 191.13,77.3 191.13,78.58 R5.2 | v175.89,86.19 175.89,88.73 BYP21.1 | v179.7,89.37 179.7,100.8 180.34,101.44 180.34,103.97 JP2.2 | v196.21,79.21 196.21,83.02 IC21.8 | v178.43,56.35 178.43,54.45 R6.2 | IC17.36 196.21,63.34 196.21,62.06 IC17.35 197.48,61.43 198.75,60.16 198.75,54.45 BYP28.1 | v186.05,61.43 v186.05,56.35
  Top 0.508: IC18.14 206.37,21.42 v206.37,29.68 v206.37,43.65 206.37,53.81 | 206.37,53.81 v206.37,66.51 206.37,68.41 205.73,69.05 205.73,83.66 IC21.12 | v205.73,53.81 206.37,53.81 | 137.79,76.03 v138.42,75.4 | 137.79,76.03 137.79,80.48 IC23.28 137.79,83.02 137.79,85.56 IC29.1 137.79,88.1 137.79,100.8 IC29.28 | R7.2 139.69,84.29 139.69,82.39 IC23.27 | v114.93,13.17 v114.93,25.87 v114.93,29.04 v114.93,38.57 114.93,42.38 114.3,43.02 114.3,45.55 112.39,47.46 112.39,50 IC14.11 | v115.56,65.24 114.93,65.24 114.93,55.08 | 114.93,55.08 114.93,52.54 v115.56,51.91 | v173.35,13.17 v173.35,5.55 | v178.43,13.17 178.43,11.27 R12.2 | IC27.14 175.89,23.96 175.89,25.23 BYP27.1 175.89,26.5 v175.89,36.66 | v188.59,10.63 188.59,17.61 R2.2 188.59,18.88 188.59,20.15 R1.2 188.59,21.42 v188.59,23.33 | v172.08,23.33 v172.08,15.71 | BYP20.1 133.98,21.42 133.98,22.7 C10.1 133.98,23.96 v133.98,33.49 | v139.06,36.66 139.06,34.76 IC20.16 138.42,34.12 137.79,34.76 137.79,44.92 IC22.1 137.79,47.46 v137.79,55.08 137.79,60.16 IC22.28 137.79,62.7 137.79,65.24 IC23.1 137.79,67.78 137.79,76.03 | v115.56,55.08 114.93,55.08 | v191.13,29.68 191.13,23.96 BYP17.1
  Bottom 0.508: BYP14.1 87.62,51.27 88.89,51.27 IC14.20 89.53,50 89.53,48.73 95.24,48.73 v95.88,49.37 | IC11.20 88.89,13.17 87.62,13.17 BYP11.1 86.35,13.17 v84.45,13.17 | v84.45,38.57 86.35,38.57 BYP13.1 87.62,38.57 88.89,38.57 IC13.20 89.53,39.84 90.8,41.11 v94.61,41.11 | v97.15,84.29 99.05,84.29 R14.2 | BYP16.1 87.62,76.67 88.89,76.67 IC16.20 | 93.34,73.5 93.34,67.78 90.8,65.24 89.53,65.24 IC15.20 88.89,63.97 87.62,63.97 BYP15.1 86.35,63.97 78.1,63.97 74.92,60.8 74.29,60.8 73.66,60.16 73.66,59.52 72.38,58.25 | 93.34,73.5 90.16,73.5 v89.53,74.13 | v61.59,58.89 62.23,58.25 72.38,58.25 | 93.34,73.5 v95.88,73.5 | v80,56.35 78.1,58.25 72.38,58.25 | BYP5.1 13.97,63.97 15.24,63.97 IC5.20 | BYP4.1 13.97,51.27 15.24,51.27 IC4.20 | BYP2.1 13.97,25.87 15.24,25.87 IC2.20 | IC1.20 15.24,13.17 13.97,13.17 BYP1.1 13.33,12.54 12.7,11.9 v5.08,11.9 | IC3.20 15.24,38.57 13.97,38.57 BYP3.1 12.7,38.57 v5.08,38.57 | v5.08,20.79 v5.08,18.25 | IC26.20 48.26,56.35 46.98,56.35 BYP26.1 45.72,56.35 v43.81,56.35 | BYP9.1 44.45,20.79 45.72,20.79 IC9.24 | BYP10.1 44.45,43.65 45.72,43.65 IC10.24 | BYP25.1 46.98,76.67 48.26,76.67 IC25.20 | BYP8.1 13.97,102.07 15.24,102.07 IC8.20 | BYP6.1 13.97,76.67 15.24,76.67 IC6.20 | BYP7.1 13.97,89.37 15.24,89.37 IC7.20 15.87,90.64 17.14,91.91 45.72,91.91 BYP24.1 | v46.35,24.6 46.98,23.96 75.56,23.96 76.83,25.23 78.1,25.23 v78.73,25.87 v84.45,25.87 86.35,25.87 BYP12.1 87.62,25.87 88.89,25.87 IC12.20 89.53,27.14 90.16,27.77 93.97,27.77 94.61,28.41 113.66,28.41 114.3,29.04 v114.93,29.04 | 196.84,86.19 196.21,85.56 IC21.8 | 200.66,86.19 196.84,86.19 | 200.66,86.19 201.29,85.56 IC21.10
  Bottom 0.508: 200.66,86.19 205.73,86.19 206.37,85.56 IC21.12 | 196.84,86.19 v175.89,86.19 | v179.7,89.37 176.53,89.37 BYP21.1 | v196.21,79.21 191.76,79.21 R5.2 | v178.43,56.35 179.7,56.35 IC17.8 182.24,56.35 v186.05,56.35 | BYP28.1 198.75,53.17 200.66,53.17 IC28.6 202.56,53.81 v205.73,53.81 | v186.05,61.43 194.94,61.43 IC17.35 | v206.37,43.65 207.64,43.65 IC19.16 | 199.38,29.68 198.75,30.31 BYP19.1 | v206.37,29.68 199.38,29.68 | v206.37,66.51 207.64,66.51 IC28.16 | BYP29.1 135.88,102.07 137.16,102.07 IC29.28 138.42,102.07 139.69,102.07 IC29.27 | v138.42,75.4 119.38,75.4 118.74,76.03 118.74,77.3 118.1,77.94 112.39,77.94 IC16.11 | BYP23.1 135.88,81.75 137.16,81.75 IC23.28 138.42,81.75 139.69,81.75 IC23.27 | v114.93,13.17 113.02,13.17 IC11.11 | v114.93,25.87 113.02,25.87 IC12.11 | v114.93,38.57 113.02,38.57 IC13.11 | v115.56,65.24 112.39,65.24 IC15.11 | v115.56,51.91 114.93,51.27 113.02,51.27 IC14.11 | R12.2 179.06,10.63 180.34,10.63 R3.2 | v173.35,5.55 175.25,5.55 R9.2 | v178.43,13.17 177.16,13.17 IC27.10 174.62,13.17 v173.35,13.17 170.81,13.17 168.91,15.08 IC27.4 169.54,15.71 v172.08,15.71 | BYP17.1 190.5,23.33 v188.59,23.33 177.16,23.33 IC27.14 174.62,23.33 v172.08,23.33 | v188.59,10.63 195.57,10.63 BYP18.1 | IC22.28 137.16,61.43 135.88,61.43 BYP22.1 | v133.98,33.49 138.42,33.49 IC20.16 | v175.89,36.66 v139.06,36.66 | v137.79,55.08 v115.56,55.08 | 199.38,29.68 v191.13,29.68
VMA  (via drill 0.61)
  Top 0.254: v210.18,8.09 210.18,24.6 210.81,25.23 210.81,29.68 212.72,31.58 212.72,54.45 v212.09,55.08
  Bottom 0.254: v210.18,8.09 207.64,8.09 IC18.9 | v212.09,55.08 214.62,57.62 214.62,62.7 194.31,62.7 193.03,63.97 182.24,63.97 IC17.5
